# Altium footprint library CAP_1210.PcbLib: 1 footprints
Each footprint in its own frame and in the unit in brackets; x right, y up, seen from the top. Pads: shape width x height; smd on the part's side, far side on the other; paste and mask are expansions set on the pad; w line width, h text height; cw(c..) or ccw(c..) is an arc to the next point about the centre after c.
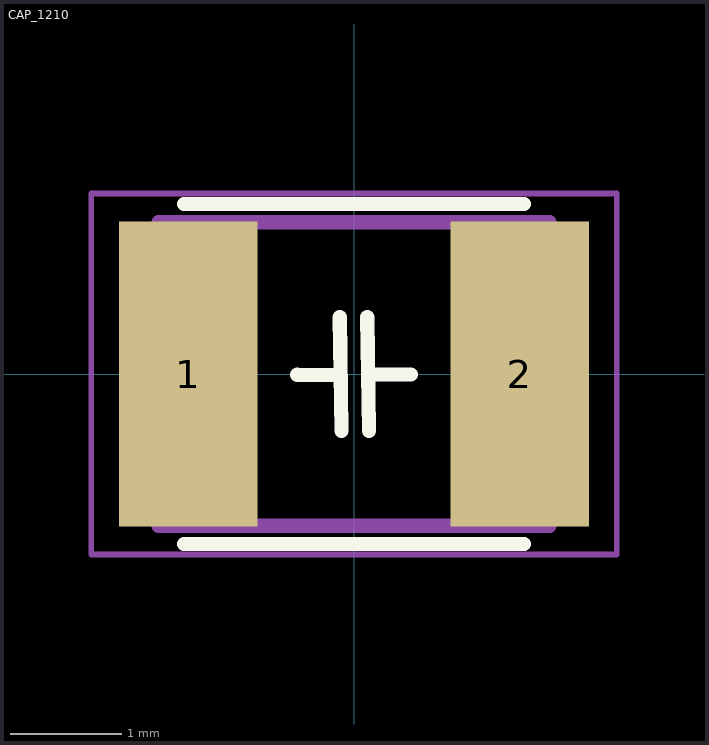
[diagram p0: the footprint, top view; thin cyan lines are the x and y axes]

## CAP_1210 [mm]
pads (2):
  rect 1.24x2.73 smd: 1(-1.485,0) 2(1.485,0)
Top Overlay:
  lines w0.127: -1.524,-1.524 1.524,-1.524 ; -1.524,1.524 1.524,1.524 ; -0.508,-0.007 -0.12,-0.008 ; -0.128,0.508 -0.113,-0.508 ; 0.119,0.508 0.134,-0.508 ; 0.153,-0.004 0.508,-0.004
Mechanical 13:
  lines w0.127: -1.75,-1.36 -1.75,1.36 1.75,1.36 1.75,-1.36 -1.75,-1.36
Mechanical 15:
  lines w0.05: -2.355,-1.617 -2.355,1.617 2.355,1.617 2.355,-1.617 -2.355,-1.617
3D body "CAP_1210.STEP": height 1.97, standoff -0.03, extent -1.596,-1.241 1.604,1.259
